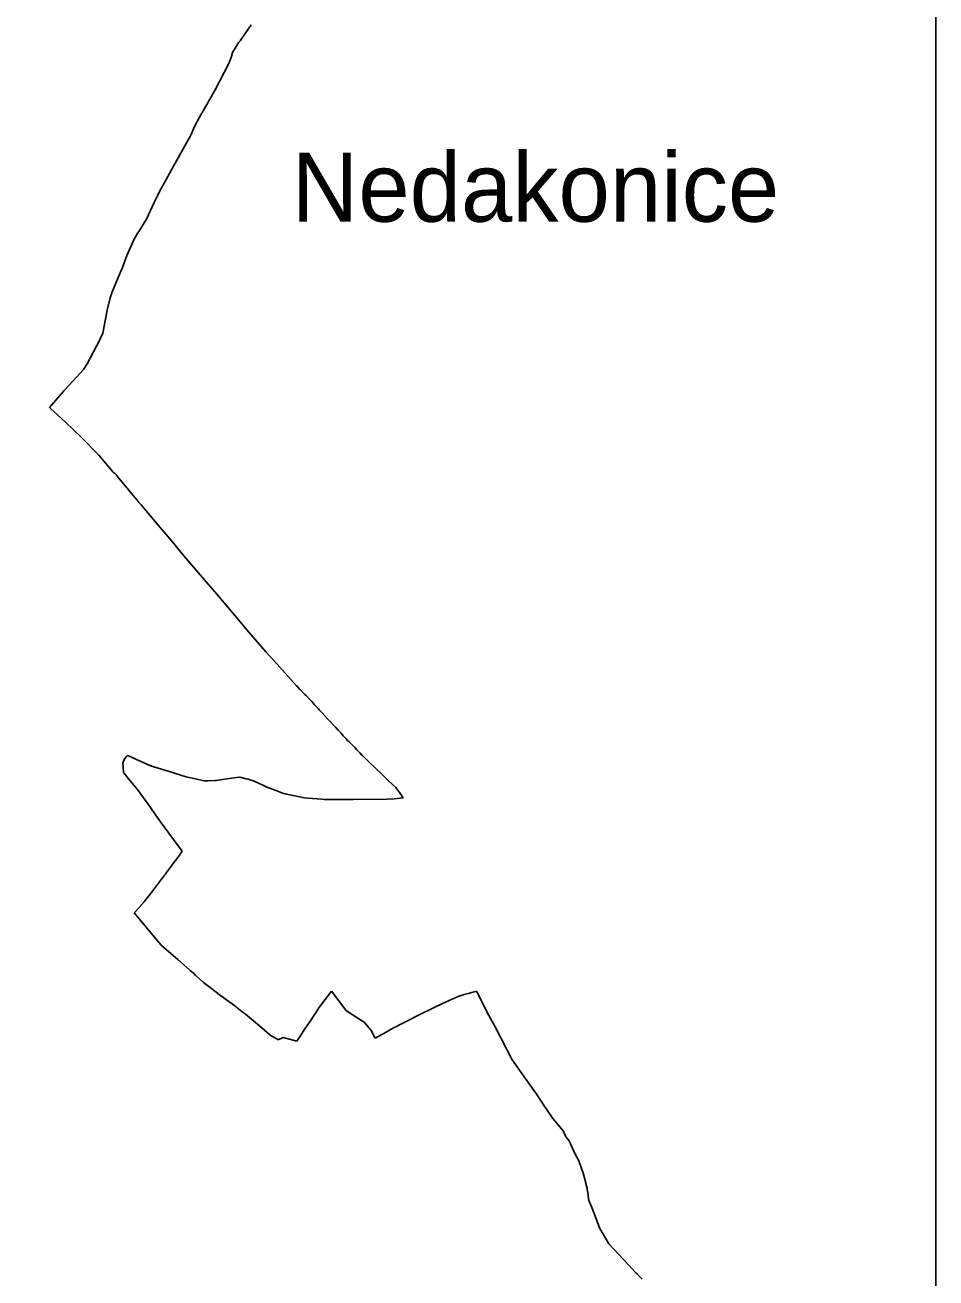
# Model space of a CAD drawing. Extents: x -552716 to -540720, y -1192685 to -1177912.
# Drawn here: x -545699 to -543896, y -1186025 to -1183546 of the extents above; entities that cross this region are included whole.
import ezdxf

# ---------------------------------------------------------------- set-up
doc = ezdxf.new("R2010")
doc.units = 0
doc.layers.add('Vrstva 1', color=7, linetype='Continuous')
doc.layers.add('Vrstva 60', color=7, linetype='Continuous')

msp = doc.modelspace()

# ---------------------------------------------------------------- linework, layer by layer
at = {"layer": 'Vrstva 1'}
for p, q in [((-545263.3, -1183562.3), (-545273.5, -1183577)), ((-545251.8, -1183545.4), (-545263.3, -1183562.3)), ((-545276.3, -1183579.8), (-545288.6, -1183600.3)), ((-545274.5, -1183578), (-545276.3, -1183579.8)), ((-545273.5, -1183577), (-545274.5, -1183578)), ((-545291.4, -1183610), (-545296.7, -1183622.8)), ((-545288.6, -1183600.3), (-545291.4, -1183610)), ((-545296.7, -1183622.8), (-545323.2, -1183674)), ((-545323.2, -1183674), (-545337.1, -1183698.4)), ((-545337.1, -1183698.4), (-545351.5, -1183723.1)), ((-545358.8, -1183736.6), (-545363.6, -1183746.6)), ((-545351.5, -1183723.1), (-545358.8, -1183736.6)), ((-545363.6, -1183746.6), (-545371.1, -1183763.7)), ((-545371.1, -1183763.7), (-545409, -1183831.1)), ((-545409, -1183831.1), (-545420.7, -1183852.8)), ((-545420.7, -1183852.8), (-545432.9, -1183875.2)), ((-545437.1, -1183883.9), (-545444.6, -1183898.1)), ((-545432.9, -1183875.2), (-545437.1, -1183883.9)), ((-545444.6, -1183898.1), (-545458, -1183928.8)), ((-545458, -1183928.8), (-545473, -1183952)), ((-545477.3, -1183958.7), (-545483.9, -1183970.5)), ((-545473, -1183952), (-545477.3, -1183958.7)), ((-545483.9, -1183970.5), (-545497.5, -1184002)), ((-545497.5, -1184002), (-545506.6, -1184025.6)), ((-545506.6, -1184025.6), (-545514.8, -1184045.6)), ((-545514.8, -1184045.6), (-545527.3, -1184075.7)), ((-545527.3, -1184075.7), (-545530.7, -1184085.6)), ((-545530.7, -1184085.6), (-545537, -1184109.8)), ((-545537, -1184109.8), (-545545.2, -1184155.2)), ((-545545.2, -1184155.2), (-545555.8, -1184177.8)), ((-545557.6, -1184181.1), (-545576.4, -1184215.9)), ((-545555.8, -1184177.8), (-545557.6, -1184181.1)), ((-545583.6, -1184227.3), (-545604.2, -1184249.9)), ((-545576.4, -1184215.9), (-545583.6, -1184227.3)), ((-545604.2, -1184249.9), (-545621.7, -1184268.9)), ((-545621.7, -1184268.9), (-545634.1, -1184283.2)), ((-545634.1, -1184283.2), (-545651.1, -1184302.5)), ((-545651.1, -1184302.5), (-545649.3, -1184304.1)), ((-545649.3, -1184304.1), (-545619.4, -1184331.9)), ((-545619.4, -1184331.9), (-545588.3, -1184361.2)), ((-545588.3, -1184361.2), (-545553.3, -1184396.7)), ((-545553.3, -1184396.7), (-545524.6, -1184430.3)), ((-545524.6, -1184430.3), (-545521.8, -1184433.3)), ((-545521.8, -1184433.3), (-545517.8, -1184437.5)), ((-545517.8, -1184437.5), (-545517.1, -1184438.4)), ((-545517.1, -1184438.4), (-545516.7, -1184438.8)), ((-545516.7, -1184438.8), (-545494.5, -1184465.6)), ((-545494.5, -1184465.6), (-545474.7, -1184489.3)), ((-545474.7, -1184489.3), (-545473.8, -1184490.4)), ((-545473.8, -1184490.4), (-545469.7, -1184495.2)), ((-545469.7, -1184495.2), (-545469.5, -1184495.4)), ((-545469.5, -1184495.4), (-545435.8, -1184535.2)), ((-545435.8, -1184535.2), (-545408.3, -1184568)), ((-545408.3, -1184568), (-545385, -1184595.9)), ((-545385, -1184595.9), (-545344.7, -1184643)), ((-545344.7, -1184643), (-545315.7, -1184676.6)), ((-545315.7, -1184676.6), (-545279.8, -1184719.1)), ((-545279.8, -1184719.1), (-545260.5, -1184742.6)), ((-545260.5, -1184742.6), (-545231.1, -1184776.5)), ((-545231.1, -1184776.5), (-545222.4, -1184786.2)), ((-545222.4, -1184786.2), (-545207.1, -1184803.1)), ((-545207.1, -1184803.1), (-545162, -1184853.2)), ((-545162, -1184853.2), (-545159.6, -1184855.7)), ((-545159.6, -1184855.7), (-545158.5, -1184856.8)), ((-545158.5, -1184856.8), (-545155.1, -1184860.5)), ((-545155.1, -1184860.5), (-545154.1, -1184861.5)), ((-545154.1, -1184861.5), (-545152.8, -1184863)), ((-545152.8, -1184863), (-545147.3, -1184868.4)), ((-545147.3, -1184868.4), (-545145.3, -1184870.4)), ((-545145.3, -1184870.4), (-545142.3, -1184873.5)), ((-545142.3, -1184873.5), (-545136.9, -1184879.3)), ((-545136.9, -1184879.3), (-545131.9, -1184884.6)), ((-545131.9, -1184884.6), (-545128.6, -1184888.2)), ((-545128.6, -1184888.2), (-545126.7, -1184890.2)), ((-545126.7, -1184890.2), (-545121.6, -1184895.8)), ((-545121.6, -1184895.8), (-545119.3, -1184898.3)), ((-545119.3, -1184898.3), (-545116.4, -1184901.5)), ((-545116.4, -1184901.5), (-545111.2, -1184907)), ((-545111.2, -1184907), (-545105.7, -1184912.9)), ((-545105.7, -1184912.9), (-545100.4, -1184918.5)), ((-545100.4, -1184918.5), (-545095.8, -1184923.5)), ((-545095.8, -1184923.5), (-545095.2, -1184924.1)), ((-545095.2, -1184924.1), (-545090, -1184929.8)), ((-545090, -1184929.8), (-545085, -1184935.2)), ((-545085, -1184935.2), (-545084.2, -1184936.1)), ((-545084.2, -1184936.1), (-545079.6, -1184941.1)), ((-545079.6, -1184941.1), (-545078.4, -1184942.5)), ((-545078.4, -1184942.5), (-545074.5, -1184946.6)), ((-545074.5, -1184946.6), (-545069.3, -1184952.2)), ((-545069.3, -1184952.2), (-545064, -1184957.8)), ((-545064, -1184957.8), (-545060, -1184962.1)), ((-545060, -1184962.1), (-545058.4, -1184963.7)), ((-545058.4, -1184963.7), (-545053.2, -1184969)), ((-545053.2, -1184969), (-545047.9, -1184974.4)), ((-545047.9, -1184974.4), (-545046.7, -1184975.7)), ((-545046.7, -1184975.7), (-545042.2, -1184980.3)), ((-545502.5, -1184998), (-545504.3, -1185002.7)), ((-545502, -1184997.5), (-545502.5, -1184998)), ((-545497.6, -1184992.8), (-545502, -1184997.5)), ((-545496.5, -1184991.7), (-545497.6, -1184992.8)), ((-545491.5, -1184993.5), (-545496.5, -1184991.7)), ((-545487.4, -1184995.1), (-545491.5, -1184993.5)), ((-545450.7, -1185011.7), (-545487.4, -1184995.1)), ((-545042.2, -1184980.3), (-545036.9, -1184985.8)), ((-545036.9, -1184985.8), (-545036.7, -1184986)), ((-545036.7, -1184986), (-545032.5, -1184990.4)), ((-545032.5, -1184990.4), (-545031.6, -1184991.3)), ((-545031.6, -1184991.3), (-545026, -1184996.7)), ((-545026, -1184996.7), (-545020.2, -1185002.3)), ((-545504.3, -1185002.7), (-545505.9, -1185006.8)), ((-545505.9, -1185006.8), (-545505.1, -1185015.2)), ((-545505.1, -1185015.2), (-545504.2, -1185024.3)), ((-545504.2, -1185024.3), (-545504, -1185025.8)), ((-545504, -1185025.8), (-545493.7, -1185038.3)), ((-545416.3, -1185022.6), (-545450.7, -1185011.7)), ((-545380.3, -1185033.3), (-545416.3, -1185022.6)), ((-545020.2, -1185002.3), (-545014.8, -1185007.6)), ((-545014.8, -1185007.6), (-545009, -1185013.2)), ((-545009, -1185013.2), (-545006, -1185016.1)), ((-545006, -1185016.1), (-545003.2, -1185018.8)), ((-545003.2, -1185018.8), (-544995.8, -1185025.9)), ((-544995.8, -1185025.9), (-544987.8, -1185033.6)), ((-545493.7, -1185038.3), (-545474.5, -1185061.4)), ((-545368.3, -1185036.2), (-545380.3, -1185033.3)), ((-545362.1, -1185037.7), (-545368.3, -1185036.2)), ((-545345.7, -1185041.2), (-545362.1, -1185037.7)), ((-545337, -1185041.7), (-545345.7, -1185041.2)), ((-545323.9, -1185041.1), (-545337, -1185041.7)), ((-545320.6, -1185040.6), (-545323.9, -1185041.1)), ((-545308.3, -1185039), (-545320.6, -1185040.6)), ((-545300.1, -1185037.7), (-545308.3, -1185039)), ((-545294.4, -1185036.7), (-545300.1, -1185037.7)), ((-545280.7, -1185035.1), (-545294.4, -1185036.7)), ((-545274.4, -1185034.4), (-545280.7, -1185035.1)), ((-545261.8, -1185037.4), (-545274.4, -1185034.4)), ((-545257.9, -1185038.5), (-545261.8, -1185037.4)), ((-545245.9, -1185042), (-545257.9, -1185038.5)), ((-545238.3, -1185045.6), (-545245.9, -1185042)), ((-545227, -1185050.7), (-545238.3, -1185045.6)), ((-545220.8, -1185053.8), (-545227, -1185050.7)), ((-544987.8, -1185033.6), (-544979.8, -1185041.2)), ((-544979.8, -1185041.2), (-544972.1, -1185048.5)), ((-544972.1, -1185048.5), (-544965.3, -1185055)), ((-545474.5, -1185061.4), (-545470.1, -1185067.6)), ((-545470.1, -1185067.6), (-545452.3, -1185092.4)), ((-545204.5, -1185060), (-545220.8, -1185053.8)), ((-545187.6, -1185066.5), (-545204.5, -1185060)), ((-545182.9, -1185067.5), (-545187.6, -1185066.5)), ((-545182, -1185067.7), (-545182.9, -1185067.5)), ((-545168.7, -1185070.6), (-545182, -1185067.7)), ((-545155.9, -1185073.3), (-545168.7, -1185070.6)), ((-545145.9, -1185075.4), (-545155.9, -1185073.3)), ((-545139.8, -1185075.9), (-545145.9, -1185075.4)), ((-544950.8, -1185075.2), (-544968.5, -1185077)), ((-544965.3, -1185055), (-544964.2, -1185056.6)), ((-544964.2, -1185056.6), (-544958.3, -1185064.8)), ((-544958.3, -1185064.8), (-544950.8, -1185075.2)), ((-545452.3, -1185092.4), (-545440.8, -1185108.9)), ((-545111.8, -1185077.8), (-545139.8, -1185075.9)), ((-545106.3, -1185078.2), (-545111.8, -1185077.8)), ((-545104.9, -1185078.3), (-545106.3, -1185078.2)), ((-545088.1, -1185078.4), (-545104.9, -1185078.3)), ((-545084.3, -1185078.4), (-545088.1, -1185078.4)), ((-545049.9, -1185078.6), (-545084.3, -1185078.4)), ((-544982.4, -1185077.9), (-545049.9, -1185078.6)), ((-544968.5, -1185077), (-544982.4, -1185077.9)), ((-545440.8, -1185108.9), (-545430.9, -1185122.8)), ((-545430.9, -1185122.8), (-545424, -1185132.5)), ((-545424, -1185132.5), (-545405.7, -1185157.5)), ((-545405.7, -1185157.5), (-545388.4, -1185181)), ((-545399.1, -1185196), (-545404.5, -1185203)), ((-545393.3, -1185188.4), (-545399.1, -1185196)), ((-545388.4, -1185181), (-545393.3, -1185188.4)), ((-545419.3, -1185222.7), (-545421.6, -1185226)), ((-545415.6, -1185217.5), (-545419.3, -1185222.7)), ((-545409.6, -1185209.7), (-545415.6, -1185217.5)), ((-545404.5, -1185203), (-545409.6, -1185209.7)), ((-545439.1, -1185249.1), (-545445.2, -1185257.2)), ((-545433.2, -1185241.3), (-545439.1, -1185249.1)), ((-545427.4, -1185233.7), (-545433.2, -1185241.3)), ((-545423.5, -1185228.5), (-545427.4, -1185233.7)), ((-545421.6, -1185226), (-545423.5, -1185228.5)), ((-545454.3, -1185269), (-545459.4, -1185275.6)), ((-545449.9, -1185263.4), (-545454.3, -1185269)), ((-545445.2, -1185257.2), (-545449.9, -1185263.4)), ((-545473.3, -1185291.9), (-545483, -1185302.8)), ((-545463.7, -1185281), (-545473.3, -1185291.9)), ((-545463.4, -1185280.7), (-545463.7, -1185281)), ((-545459.4, -1185275.6), (-545463.4, -1185280.7)), ((-545483, -1185302.8), (-545429.6, -1185367)), ((-545429.6, -1185367), (-545428.6, -1185367.9)), ((-545428.6, -1185367.9), (-545419.8, -1185375.6)), ((-545419.8, -1185375.6), (-545397.1, -1185395.4)), ((-545397.1, -1185395.4), (-545373.5, -1185415.6)), ((-545373.5, -1185415.6), (-545372.4, -1185416.6)), ((-545372.4, -1185416.6), (-545366.1, -1185422.5)), ((-545366.1, -1185422.5), (-545361.6, -1185426.6)), ((-545361.6, -1185426.6), (-545361.2, -1185427.1)), ((-545361.2, -1185427.1), (-545351.9, -1185435.5)), ((-545351.9, -1185435.5), (-545345.9, -1185440.8)), ((-545345.9, -1185440.8), (-545342.6, -1185443.4)), ((-545342.6, -1185443.4), (-545333.1, -1185450.6)), ((-545333.1, -1185450.6), (-545323.3, -1185458)), ((-545323.3, -1185458), (-545312.6, -1185466.2)), ((-545312.6, -1185466.2), (-545305.9, -1185471.2)), ((-545305.9, -1185471.2), (-545302.6, -1185473.6)), ((-545117.5, -1185491.1), (-545092.8, -1185457.8)), ((-545092.8, -1185457.8), (-545066, -1185493)), ((-544871.6, -1185481.4), (-544842.2, -1185468.2)), ((-544842.2, -1185468.2), (-544841.2, -1185467.9)), ((-544841.2, -1185467.9), (-544839.7, -1185467.5)), ((-544839.7, -1185467.5), (-544830.2, -1185464.7)), ((-544830.2, -1185464.7), (-544819.2, -1185461.6)), ((-544819.2, -1185461.6), (-544805.7, -1185457.7)), ((-544805.7, -1185457.7), (-544781.2, -1185505.7)), ((-545302.6, -1185473.6), (-545295.8, -1185478.4)), ((-545295.8, -1185478.4), (-545289.6, -1185482.6)), ((-545289.6, -1185482.6), (-545281.2, -1185489.1)), ((-545281.2, -1185489.1), (-545279.1, -1185490.8)), ((-545279.1, -1185490.8), (-545273.2, -1185495.4)), ((-545273.2, -1185495.4), (-545269.9, -1185497.9)), ((-545134.5, -1185516.6), (-545118.1, -1185492)), ((-545118.1, -1185492), (-545117.5, -1185491.1)), ((-545066, -1185493), (-545063.8, -1185495.8)), ((-545063.8, -1185495.8), (-545062.8, -1185496.5)), ((-545062.8, -1185496.5), (-545027.3, -1185519.9)), ((-544917.6, -1185504.3), (-544893.6, -1185492.3)), ((-544893.6, -1185492.3), (-544873.1, -1185482)), ((-544873.1, -1185482), (-544871.6, -1185481.4)), ((-545269.9, -1185497.9), (-545263, -1185503.4)), ((-545263, -1185503.4), (-545235.4, -1185526.1)), ((-545139.5, -1185524.1), (-545134.5, -1185516.6)), ((-545027.3, -1185519.9), (-545014.7, -1185534.9)), ((-544956.6, -1185523.9), (-544941.9, -1185516.5)), ((-544941.9, -1185516.5), (-544917.6, -1185504.3)), ((-544781.2, -1185505.7), (-544768.9, -1185528.4)), ((-545235.4, -1185526.1), (-545215.4, -1185543.5)), ((-545215.4, -1185543.5), (-545212.7, -1185545.8)), ((-545212.7, -1185545.8), (-545211.9, -1185546.3)), ((-545211.9, -1185546.3), (-545210.6, -1185547)), ((-545161.3, -1185556.8), (-545139.5, -1185524.1)), ((-545014.7, -1185534.9), (-545014.2, -1185535.8)), ((-545014.2, -1185535.8), (-545005.9, -1185550.8)), ((-545005.9, -1185550.8), (-544985.7, -1185539.5)), ((-544985.7, -1185539.5), (-544969.9, -1185530.7)), ((-544969.9, -1185530.7), (-544964.2, -1185527.7)), ((-544964.2, -1185527.7), (-544956.6, -1185523.9)), ((-544768.9, -1185528.4), (-544734.9, -1185593.4)), ((-545210.6, -1185547), (-545209.2, -1185547.8)), ((-545209.2, -1185547.8), (-545203.8, -1185550.8)), ((-545203.8, -1185550.8), (-545201, -1185552.4)), ((-545201, -1185552.4), (-545198.1, -1185554.1)), ((-545198.1, -1185554.1), (-545188.6, -1185549.6)), ((-545188.6, -1185549.6), (-545161.3, -1185556.8)), ((-544734.9, -1185593.4), (-544688.1, -1185659.4)), ((-544688.1, -1185659.4), (-544687.4, -1185660.5)), ((-544687.4, -1185660.5), (-544671.5, -1185684.6)), ((-544671.5, -1185684.6), (-544657.2, -1185706.1)), ((-544657.2, -1185706.1), (-544656.2, -1185707.4)), ((-544656.2, -1185707.4), (-544654.3, -1185709.7)), ((-544654.3, -1185709.7), (-544634, -1185734.4)), ((-544634, -1185734.4), (-544633.4, -1185735.8)), ((-544633.4, -1185735.8), (-544629.6, -1185744.7)), ((-544629.6, -1185744.7), (-544628.1, -1185746.5)), ((-544628.1, -1185746.5), (-544622, -1185754.3)), ((-544622, -1185754.3), (-544611, -1185779.1)), ((-544611, -1185779.1), (-544602.9, -1185793.9)), ((-544602.9, -1185793.9), (-544594.5, -1185817.9)), ((-544594.5, -1185817.9), (-544590.1, -1185834.3)), ((-544590.1, -1185834.3), (-544589.7, -1185836)), ((-544589.7, -1185836), (-544587.1, -1185845.5)), ((-544587.1, -1185845.5), (-544586.8, -1185847.4)), ((-544586.8, -1185847.4), (-544586.4, -1185850.4)), ((-544586.4, -1185850.4), (-544585.4, -1185856.4)), ((-544585.4, -1185856.4), (-544583.6, -1185868.5)), ((-544583.6, -1185868.5), (-544583, -1185872.2)), ((-544583, -1185872.2), (-544577.5, -1185886.3)), ((-544577.5, -1185886.3), (-544569.7, -1185906.4)), ((-544569.7, -1185906.4), (-544564.2, -1185920.8)), ((-544564.2, -1185920.8), (-544561.4, -1185927.8)), ((-544561.4, -1185927.8), (-544543.7, -1185957.7)), ((-544543.7, -1185957.7), (-544504.8, -1185999.2)), ((-544504.8, -1185999.2), (-544489.3, -1186015.7)), ((-544489.3, -1186015.7), (-544488.2, -1186016.8)), ((-544488.2, -1186016.8), (-544482.7, -1186022.8)), ((-544482.7, -1186022.8), (-544477.8, -1186027.9))]:
    msp.add_line(p, q, dxfattribs=at)
at = {"layer": 'Vrstva 60'}
msp.add_lwpolyline([(-543896.1, -1181161.6), (-549696, -1181161.6), (-549696, -1188366.4), (-543896.1, -1188366.4)], close=True, dxfattribs=at)

# ---------------------------------------------------------------- texts
at = {"layer": 'Vrstva 1'}
msp.add_text('Nedakonice', height=136.69, dxfattribs=at).set_placement((-545171.6, -1183934.9))

doc.saveas('drawing.dxf')
